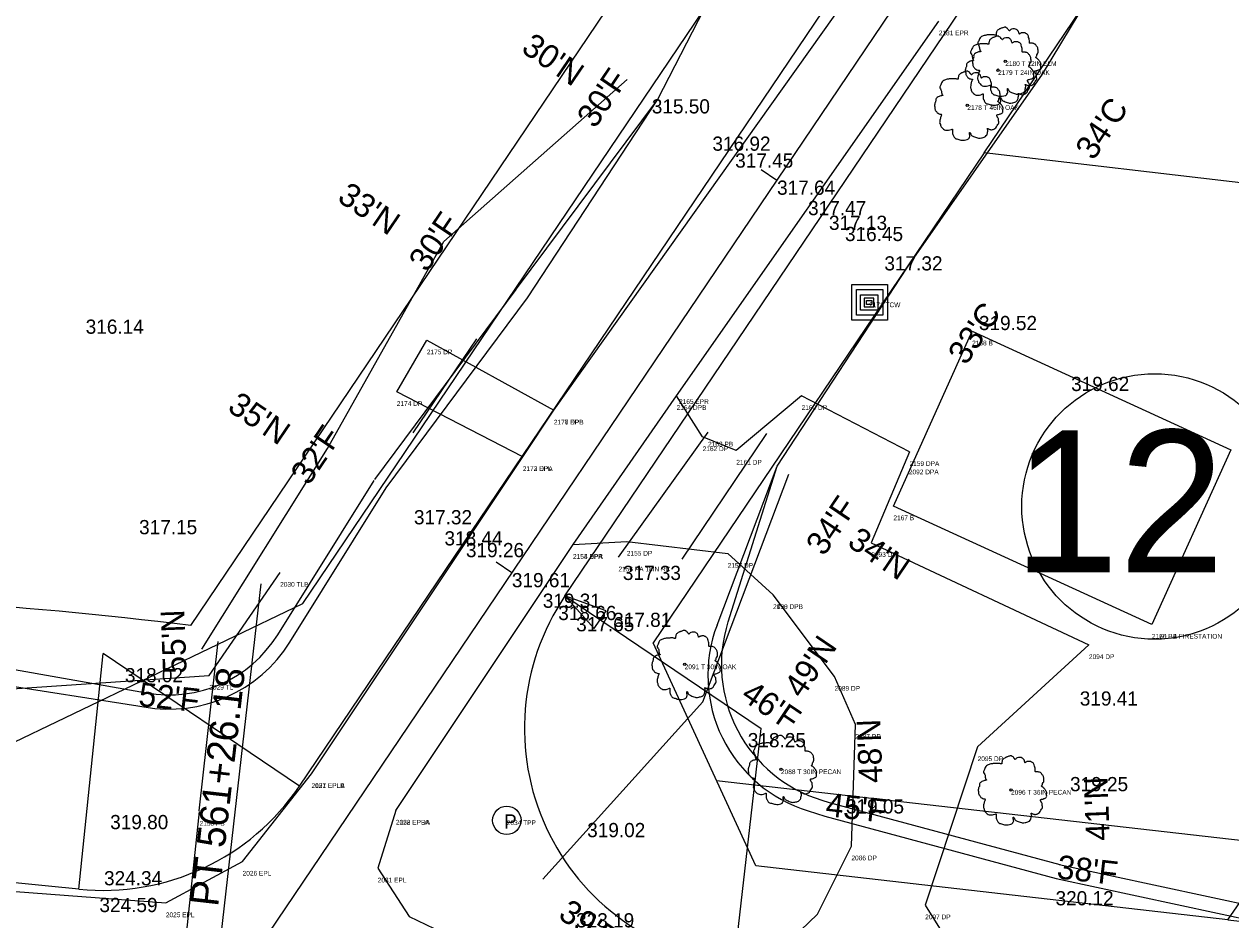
# Model space of a CAD drawing. Extents: x 49683 to 58852, y 49525 to 54803.
# Drawn here: x 56880.6 to 57135.4, y 54072.5 to 54261.8 of the extents above; entities that cross this region are included whole.
import ezdxf

# ---------------------------------------------------------------- set-up
doc = ezdxf.new("R2010")
doc.units = 0
for name, color, linetype in [('Level 1', 7, 'Continuous'), ('Level 11', 7, 'Continuous'), ('Level 12', 7, 'Continuous'), ('Level 13', 7, 'Continuous'), ('Level 18', 7, 'Continuous'), ('Level 20', 7, 'Continuous'), ('Level 21', 7, 'Continuous'), ('Level 24', 7, 'Continuous'), ('Level 25', 7, 'Continuous'), ('Level 3', 7, 'Continuous'), ('Level 32', 7, 'Continuous'), ('Level 33', 7, 'Continuous'), ('Level 34', 7, 'Continuous'), ('Level 48', 7, 'Continuous'), ('Level 53', 7, 'Continuous'), ('Level 56', 7, 'Continuous'), ('Level 58', 7, 'Continuous'), ('Level 59', 7, 'Continuous'), ('Level 6', 7, 'Continuous'), ('Level 61', 7, 'Continuous'), ('Level 8', 7, 'Continuous'), ('Level 9', 7, 'Continuous')]:
    doc.layers.add(name, color=color, linetype=linetype)

# ---------------------------------------------------------------- blocks, each defined once
blk = doc.blocks.new('TPP')
at = {"layer": 'Level 9'}
blk.add_circle((0, 0), 3, dxfattribs=at)
blk.add_text('P', height=3, dxfattribs=at).set_placement((-0.59, -1.73))
blk = doc.blocks.new('T1')
at = {"layer": 'Level 11'}
for centre, radius in [((0, 0), 0.25), ((-0.01, -0.02), 0.0001)]:
    blk.add_circle(centre, radius, dxfattribs=at)
for points in [[(0.13, 7.17), (-0.17, 7.19), (-0.49, 7.09), (-0.74, 6.99), (-0.97, 6.92), (-1.19, 6.82), (-1.49, 6.64), (-1.72, 6.44), (-1.84, 6.19), (-1.89, 5.97), (-1.94, 5.69), (-1.94, 5.52), (-2.07, 5.49), (-2.22, 5.52), (-2.47, 5.59), (-2.72, 5.59), (-2.97, 5.59), (-3.32, 5.57), (-3.67, 5.57), (-3.94, 5.52), (-4.27, 5.47), (-4.64, 5.34), (-4.99, 5.22), (-5.29, 4.97), (-5.54, 4.49), (-5.67, 4.14), (-5.82, 3.89), (-5.67, 3.44), (-5.49, 3.09), (-5.47, 2.89), (-5.39, 2.47), (-5.29, 2.24), (-5.17, 2.04), (-5.24, 2.02), (-5.62, 1.97), (-5.92, 1.87), (-6.34, 1.64), (-6.57, 1.42), (-6.67, 1.09), (-6.69, 0.75), (-6.79, 0.55), (-6.87, 0.27), (-6.89, 0.2), (-6.94, -0.13), (-6.84, -0.58), (-6.82, -0.93), (-6.69, -1.15), (-6.54, -1.33), (-6.37, -1.58), (-5.97, -1.8), (-5.64, -1.9), (-5.44, -1.93), (-5.62, -2.43), (-5.67, -2.78), (-5.79, -3.18), (-5.79, -3.25), (-5.84, -3.73), (-5.69, -4.05), (-5.62, -4.43), (-5.44, -4.65), (-5.17, -4.95), (-4.84, -5.18), (-4.34, -5.3), (-3.94, -5.28), (-3.37, -5.1), (-3.12, -5.03), (-3.14, -5.2), (-3.12, -5.58), (-3.12, -6), (-2.97, -6.33), (-2.87, -6.6), (-2.72, -6.85), (-2.39, -7.08), (-1.99, -7.15), (-1.57, -7.3), (-1.12, -7.38), (-0.62, -7.4), (-0.02, -7.25), (0.26, -7.13), (0.36, -6.95), (0.56, -6.58), (0.51, -6.35), (0.53, -5.75), (0.63, -5.93), (0.81, -6.28), (1.31, -6.58), (1.71, -6.75), (2.18, -6.9), (2.48, -6.98), (2.96, -6.9), (3.33, -6.83), (3.71, -6.7), (4.01, -6.43), (4.18, -6.15), (4.23, -5.88), (4.31, -5.5), (4.36, -5.33)], [(4.36, -5.33), (4.28, -5.15), (4.23, -4.9), (4.31, -4.93), (4.48, -4.98), (4.75, -5.1), (4.98, -5.18), (5.3, -5.15), (5.58, -5.05), (6.03, -4.78), (6.3, -4.3), (6.58, -3.9), (6.65, -3.58), (6.6, -3.35), (6.58, -2.85), (6.38, -2.6), (6.33, -2.48), (6.23, -2.08), (6.3, -2.03), (6.58, -1.98), (6.95, -1.85), (7.23, -1.73), (7.45, -1.55), (7.53, -1.33), (7.5, -0.93), (7.55, -0.53), (7.48, -0.38), (7.38, -0.23), (7.3, -0.03), (7.15, 0.12), (7.05, 0.27), (6.95, 0.37), (6.83, 0.52), (6.65, 0.65), (6.5, 0.7), (6.45, 0.85), (6.6, 1.04), (6.65, 1.14), (6.68, 1.37), (6.9, 1.72), (6.95, 2.12), (6.9, 2.54), (6.85, 2.82), (6.7, 3.09), (6.5, 3.34), (6.38, 3.52), (6.2, 3.64), (5.88, 3.77), (5.63, 3.82), (5.28, 3.82), (5.08, 3.87), (5.1, 3.92), (5.1, 4.07), (5.1, 4.34), (5.03, 4.79), (4.88, 5.29), (4.88, 5.32), (4.78, 5.57), (4.56, 5.77), (4.38, 5.87), (4.18, 5.99), (3.93, 6.02), (3.63, 6.02), (3.36, 5.97), (3.16, 5.87), (2.98, 5.74), (2.91, 5.89), (2.81, 6.19), (2.76, 6.34), (2.61, 6.52), (2.38, 6.72), (1.93, 6.84), (1.31, 6.77), (1.01, 6.57), (0.86, 6.39), (0.81, 6.52), (0.61, 6.72), (0.51, 6.89), (0.33, 7.02), (0.18, 7.12), (0.08, 7.17)]]:
    blk.add_spline(points, degree=3, dxfattribs=at)
blk = doc.blocks.new('TCW')
at = {"layer": 'Level 8'}
for points in [[(-3.64, -3.72), (-3.64, 3.78), (3.86, 3.78), (3.86, -3.72)], [(-2.65, -2.69), (-2.65, 2.76), (2.88, 2.76), (2.88, -2.69)], [(-1.86, -1.63), (-1.86, 1.59), (1.82, 1.59), (1.82, -1.63)], [(-1.03, 0.92), (-1.03, -0.89), (1.02, -0.89), (1.02, 0.92)], [(-0.55, -0.41), (-0.55, 0.42), (0.54, 0.42), (0.54, -0.41)]]:
    blk.add_lwpolyline(points, close=True, dxfattribs=at)

msp = doc.modelspace()

# ---------------------------------------------------------------- linework, layer by layer
at = {"layer": 'Level 1'}
for p, q in [((56927.66, 54062.96), (57263.35, 54560.26)), ((57039.56, 54228.72), (57036.24, 54230.96)), ((56983.61, 54145.84), (56980.29, 54148.08))]:
    msp.add_line(p, q, dxfattribs=at)
at = {"layer": 'Level 11'}
for p, q in [((56919.7, 54124.18), (56934.67, 54145.92)), ((56763.02, 54113.51), (56919.7, 54124.18))]:
    msp.add_line(p, q, dxfattribs=at)
at = {"layer": 'Level 12'}
for p, q in [((56939.44, 54139.39), (57236, 54578.72)), ((57083.33, 54234.58), (57290.7, 54541.79)), ((57083.33, 54234.58), (57013.43, 54131.04)), ((57233.86, 54217.04), (57083.33, 54234.58)), ((57134.79, 54072.57), (57233.86, 54217.04)), ((56861.63, 54101.97), (56939.44, 54139.39)), ((57035.13, 54083.93), (57013.43, 54131.04))]:
    msp.add_line(p, q, dxfattribs=at)
at = {"layer": 'Level 13'}
for q in [(57035.13, 54083.93), (58787.04, 53884.15)]:
    msp.add_line((57134.79, 54072.57), q, dxfattribs=at)
at = {"layer": 'Level 18'}
for p, q in [((57095.61, 54251.21), (57121.56, 54294.02)), ((57014.32, 54245.76), (57037.31, 54290.57)), ((57066.99, 54210.21), (57095.61, 54251.21)), ((56984.39, 54205.59), (57014.32, 54245.76)), ((56986.9, 54203.94), (57014.32, 54245.76)), ((57039.58, 54168.38), (57066.99, 54210.21)), ((56954.62, 54165.58), (56984.49, 54205.73)), ((56957.02, 54163.78), (56986.9, 54203.94)), ((57026.91, 54134.83), (57039.58, 54168.38)), ((57029.23, 54135.5), (57039.58, 54168.38)), ((56934.16, 54132.78), (56954.48, 54165.37)), ((56936.71, 54131.2), (56957.02, 54163.78)), ((56852.93, 54129.91), (56906.44, 54120.5)), ((56852.31, 54125.96), (56904.59, 54117.78)), ((56904.59, 54117.78), (56905.91, 54117.54)), ((57049.03, 54097.82), (57050.57, 54097.34)), ((57050.57, 54097.34), (57099.29, 54084.21)), ((57046.16, 54095.56), (57049.69, 54094.47)), ((57049.69, 54094.47), (57098.51, 54081.31)), ((57099.15, 54084.24), (57148.26, 54073.66)), ((57098.51, 54081.31), (57147.63, 54070.73))]:
    msp.add_line(p, q, dxfattribs=at)
for centre, radius, start, end in [((57054.98, 54124.23), 30, 159.3213, 252.9092), ((57057.84, 54126.49), 30, 162.5292, 252.9092), ((56911.25, 54147.07), 27, 259.7439, 328.0619), ((56911.25, 54147.07), 30, 259.7439, 328.0619)]:
    msp.add_arc(centre, radius, start, end, dxfattribs=at)
at = {"layer": 'Level 20'}
for p, q in [((56938.73, 54100.8), (57197.46, 54484.09)), ((56994.8, 54140.97), (57217.35, 54470.66)), ((56994.8, 54140.97), (57036.24, 54112.99)), ((56892.16, 54079.04), (56897.29, 54128.78)), ((56938.73, 54100.8), (56897.29, 54128.78)), ((57030.57, 54063.31), (57036.24, 54112.99))]:
    msp.add_line(p, q, dxfattribs=at)
for centre, radius, start, end in [((57036.24, 54112.99), 50, 145.9793, 263.4944), ((56897.29, 54128.78), 50, 264.1136, 325.9793), ((56791.96, 53107.19), 977, 84.11358, 131.63331)]:
    msp.add_arc(centre, radius, start, end, dxfattribs=at)
at = {"layer": 'Level 21'}
msp.add_line((56921.78, 54065.66), (56930.66, 54143.52), dxfattribs=at)
at = {"layer": 'Level 24'}
for p, q in [((56994.8, 54140.97), (57001, 54134.07)), ((57003.51, 54137.8), (56994.8, 54140.97)), ((57001, 54134.07), (57003.51, 54137.8))]:
    msp.add_line(p, q, dxfattribs=at)
at = {"layer": 'Level 25'}
msp.add_circle((57119.31, 54159.87), 28.04, dxfattribs=at)
at = {"layer": 'Level 3'}
for p, q in [((56992.46, 54180.19), (57057.7, 54272.01)), ((57018.37, 54183.28), (57073.74, 54262.41)), ((56996.5, 54151.81), (57018.37, 54183.28)), ((56985.91, 54170.38), (56992.46, 54180.19)), ((56941.28, 54103.41), (56985.91, 54170.38)), ((56959.1, 54095.67), (56996.5, 54151.81)), ((56926.73, 54084.89), (56941.28, 54103.41)), ((56959.1, 54095.67), (56955.26, 54083.44)), ((56910.53, 54076.11), (56926.73, 54084.89)), ((56955.26, 54083.44), (56961.87, 54073.22)), ((56872.82, 54079.01), (56910.53, 54076.11)), ((56961.87, 54073.22), (56968.94, 54069.84))]:
    msp.add_line(p, q, dxfattribs=at)
at = {"layer": 'Level 33'}
for p, q in [((56915.8, 54134.76), (57165.96, 54505.35)), ((57026.81, 54101.99), (57145.67, 54088.44))]:
    msp.add_line(p, q, dxfattribs=at)
msp.add_arc((56791.96, 53107.19), 1035, 83.12795, 95.51566, dxfattribs=at)
at = {"layer": 'Level 34'}
for p, q in [((56962.77, 54175.42), (56976.2, 54195.31)), ((57019.53, 54148.77), (57037.44, 54175.29)), ((56917.57, 54095.55), (56921.55, 54131.33))]:
    msp.add_line(p, q, dxfattribs=at)
at = {"layer": 'Level 6'}
for p, q in [((57006.1, 54149.16), (57025.02, 54175.55)), ((56912.03, 54042.18), (56917.65, 54095.42))]:
    msp.add_line(p, q, dxfattribs=at)
at = {"layer": 'Level 61'}
for p, q in [((56969.24, 54215.86), (57007.93, 54250.07)), ((56969.24, 54215.86), (57007.93, 54250.07)), ((56969.24, 54215.86), (57007.93, 54250.07)), ((56944.69, 54172.11), (56969.24, 54215.86)), ((56944.69, 54172.11), (56969.24, 54215.86)), ((56944.69, 54172.11), (56969.24, 54215.86)), ((56918.1, 54129.73), (56944.69, 54172.11)), ((56918.1, 54129.73), (56944.69, 54172.11)), ((56918.1, 54129.73), (56944.69, 54172.11)), ((57023.92, 54118.63), (57042.06, 54166.71)), ((57023.92, 54118.63), (57042.06, 54166.71)), ((57023.92, 54118.63), (57042.06, 54166.71)), ((56990.12, 54081.11), (57023.92, 54118.63)), ((56990.12, 54081.11), (57023.92, 54118.63)), ((56990.12, 54081.11), (57023.92, 54118.63))]:
    msp.add_line(p, q, dxfattribs=at)
at = {"layer": 'Level 8'}
for p, q in [((56959.3, 54184.12), (56965.64, 54195.01)), ((56965.64, 54195.01), (56992.46, 54180.19)), ((57064.15, 54159.97), (57080.78, 54196.9)), ((57080.78, 54196.9), (57135.38, 54171.87)), ((56985.91, 54170.38), (56959.3, 54184.12)), ((57023.87, 54174.56), (57018.37, 54183.28)), ((57044.77, 54183.27), (57030.98, 54171.72)), ((57067.56, 54171.43), (57044.77, 54183.27)), ((57030.98, 54171.72), (57023.87, 54174.56)), ((57067.56, 54171.43), (57059.48, 54152.2)), ((57135.38, 54171.87), (57118.74, 54134.95)), ((57118.74, 54134.95), (57064.15, 54159.97)), ((56996.5, 54151.81), (57007.87, 54152.48)), ((57007.87, 54152.48), (57029.16, 54149.92)), ((57059.48, 54152.2), (57105.44, 54130.64)), ((57029.16, 54149.92), (57038.75, 54141.21)), ((57051.73, 54123.94), (57038.75, 54141.21)), ((57105.44, 54130.64), (57081.94, 54109.08)), ((57056.12, 54113.8), (57051.73, 54123.94)), ((57055.29, 54088.12), (57056.12, 54113.8)), ((57081.94, 54109.08), (57070.86, 54075.67)), ((57048.15, 54073.76), (57055.29, 54088.12)), ((57070.86, 54075.67), (57082.6, 54056.87)), ((57036.25, 54062.34), (57048.15, 54073.76))]:
    msp.add_line(p, q, dxfattribs=at)

# ---------------------------------------------------------------- block references
at = {"layer": 'Level 11'}
for p in [(57086.26, 54252.04), (57087.77, 54253.93), (57079.76, 54244.64), (57020.08, 54126.5), (57040.41, 54104.33), (57088.99, 54100)]:
    msp.add_blockref('T1', p, dxfattribs=at)
at = {"layer": 'Level 8'}
msp.add_blockref('TCW', (57059.03, 54202.97), dxfattribs=at)
at = {"layer": 'Level 9'}
msp.add_blockref('TPP', (56982.52, 54093.56), dxfattribs=at)

# ---------------------------------------------------------------- texts
at = {"layer": 'Level 21'}
msp.add_text('PT 561+26.18', height=6, rotation=83.4944, dxfattribs=at).set_placement((56921.55, 54075.19))
at = {"layer": 'Level 25'}
msp.add_text('12', height=30, dxfattribs=at).set_placement((57089.46, 54145.99))
at = {"layer": 'Level 32'}
for s, p in [('315.50', (57013.14, 54242.9)), ('316.92', (57025.94, 54235.02)), ('317.45', (57030.74, 54231.45)), ('317.64', (57039.59, 54225.72)), ('317.47', (57046.14, 54221.41)), ('317.13', (57050.55, 54218.3)), ('316.45', (57053.93, 54215.94)), ('317.32', (57062.25, 54209.73)), ('319.52', (57082.21, 54197.13)), ('316.14', (56893.6, 54196.36)), ('319.62', (57101.68, 54184.26)), ('317.15', (56904.88, 54154.01)), ('317.32', (56962.91, 54156.1)), ('318.44', (56969.36, 54151.64)), ('319.26', (56973.89, 54149.16)), ('317.33', (57007.02, 54144.34)), ('319.61', (56983.59, 54142.81)), ('319.31', (56990.12, 54138.46)), ('318.66', (56993.38, 54135.87)), ('317.65', (56997.17, 54133.5)), ('317.81', (57004.98, 54134.43)), ('318.02', (56901.88, 54122.73)), ('319.41', (57103.51, 54117.81)), ('318.25', (57033.41, 54109.01)), ('319.25', (57101.45, 54099.72)), ('319.05', (57054.13, 54095.01)), ('319.80', (56898.77, 54091.7)), ('319.02', (56999.49, 54090.01)), ('324.34', (56897.47, 54079.84)), ('320.12', (57098.39, 54075.61)), ('324.59', (56896.5, 54074.18)), ('323.19', (56997.15, 54070.95))]:
    msp.add_text(s, height=3, dxfattribs=at).set_placement(p)
at = {"layer": 'Level 48'}
for s, rotation, p in [("30'N", 325.8114, (56985.32, 54256.05)), ("30'F", 55.9793, (57001.14, 54239.53)), ("34'C", 55.9793, (57106.4, 54232.78)), ("33'N", 325.8114, (56946.49, 54224.55)), ("30'F", 55.9793, (56965.64, 54209.17)), ("33'C", 55.9793, (57079.49, 54189.53)), ("35'N", 325.8114, (56923.29, 54180.25)), ("32'F", 55.9793, (56940.69, 54164.12)), ("34'F", 55.9793, (57049.49, 54149.19)), ("34'N", 325.8114, (57054.18, 54151.69)), ("55'N", 92.1896, (56914.93, 54124.64)), ("49'N", 55.8114, (57044.85, 54119.1)), ("52'F", 353.6409, (56904.59, 54117.78)), ("46'F", 325.9793, (57031.69, 54119.27)), ("48'N", 92.1896, (57061.88, 54101.53)), ("41'N", 92.1896, (57109.85, 54089.34)), ("45'F", 353.4944, (57049.69, 54094.47)), ("38'F", 353.4944, (57098.51, 54081.31)), ("39'F", 325.9793, (56993.13, 54073.05))]:
    msp.add_text(s, height=5, rotation=rotation, dxfattribs=at).set_placement(p)
at = {"layer": 'Level 53'}
for s, p in [('2181 EPR ', (57073.74, 54259.41)), ('2165 EPR ', (57018.88, 54181.53)), ('2177 EPL ', (56992.46, 54177.19)), ('2172 EPL ', (56985.91, 54167.38)), ('2153 EPR ', (56996.5, 54148.81)), ('2027 EPLB ', (56941.28, 54100.41)), ('2151 EPLA ', (56941.28, 54100.41)), ('2028 EPLA ', (56959.1, 54092.67)), ('2152 EPRA ', (56959.1, 54092.67)), ('2026 EPL ', (56926.73, 54081.89)), ('2031 EPL ', (56955.26, 54080.44)), ('2025 EPL ', (56910.53, 54073.11))]:
    msp.add_text(s, height=1, dxfattribs=at).set_placement(p)
at = {"layer": 'Level 56'}
for s, p in [('2163 PB ', (57025.02, 54172.55)), ('2156 PA 18IN RC ', (57006.1, 54146.16)), ('2150 PB ', (56917.65, 54092.42))]:
    msp.add_text(s, height=1, dxfattribs=at).set_placement(p)
at = {"layer": 'Level 58'}
for s, p in [('2171 TCW ', (57059.03, 54201.97)), ('2175 DP ', (56965.64, 54192.01)), ('2168 B ', (57080.78, 54193.9)), ('2174 DP ', (56959.3, 54181.12)), ('2164 DPB ', (57018.37, 54180.28)), ('2160 DP ', (57044.77, 54180.27)), ('2176 DPB ', (56992.46, 54177.19)), ('2162 DP ', (57023.87, 54171.56)), ('2161 DP ', (57030.98, 54168.72)), ('2173 DPA ', (56985.91, 54167.38)), ('2092 DPA ', (57067.42, 54166.66)), ('2159 DPA ', (57067.56, 54168.43)), ('2167 B ', (57064.15, 54156.97)), ('2154 DPA ', (56996.5, 54148.81)), ('2155 DP ', (57007.87, 54149.48)), ('2093 DP ', (57059.48, 54149.2)), ('2157 DP ', (57029.16, 54146.92)), ('2090 DPB ', (57038.75, 54138.21)), ('2158 DPB ', (57038.75, 54138.21)), ('2166 BA FIRESTATION ', (57118.74, 54131.95)), ('2170 BB ', (57118.74, 54131.95)), ('2094 DP ', (57105.44, 54127.64)), ('2089 DP ', (57051.73, 54120.94)), ('2087 DP ', (57056.12, 54110.8)), ('2095 DP ', (57081.94, 54106.08)), ('2086 DP ', (57055.29, 54085.12)), ('2097 DP ', (57070.86, 54072.67))]:
    msp.add_text(s, height=1, dxfattribs=at).set_placement(p)
at = {"layer": 'Level 59'}
msp.add_text('2034 TPP ', height=1, dxfattribs=at).set_placement((56982.52, 54092.56))
at = {"layer": 'Level 61'}
for s, p in [('2180 T 12IN ELM ', (57087.77, 54252.93)), ('2179 T 24IN OAK ', (57086.26, 54251.04)), ('2178 T 46IN OAK ', (57079.76, 54243.64)), ('2030 TLB ', (56934.67, 54142.92)), ('2091 T 30IN OAK ', (57020.08, 54125.5)), ('2029 TL ', (56919.7, 54121.18)), ('2088 T 30IN PECAN ', (57040.41, 54103.33)), ('2096 T 36IN PECAN ', (57088.99, 54099))]:
    msp.add_text(s, height=1, dxfattribs=at).set_placement(p)

doc.saveas('drawing.dxf')
